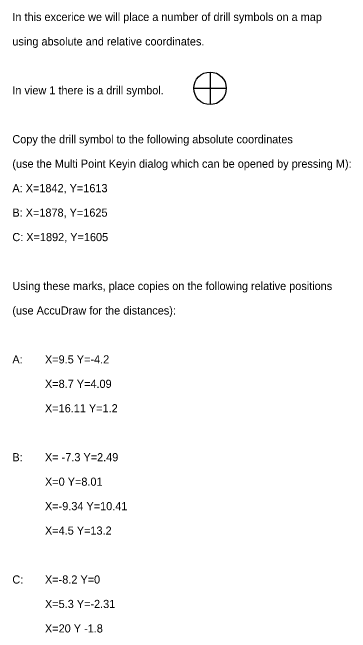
# Model space of a CAD drawing. Extents: x -2 to 1890, y 50 to 1639.
import ezdxf

# ---------------------------------------------------------------- set-up
doc = ezdxf.new("R2010")
doc.units = 0
doc.layers.add('Instruktioner', color=7, linetype='Continuous')

msp = doc.modelspace()

# ---------------------------------------------------------------- linework, layer by layer
at = {"layer": 'Instruktioner'}
for p, q in [((4.35, 66.804), (4.35, 65.804)), ((3.85, 66.304), (4.85, 66.304))]:
    msp.add_line(p, q, dxfattribs=at)
msp.add_circle((4.35, 66.304), 0.5, dxfattribs=at)

# ---------------------------------------------------------------- texts
for s, p in [('In this excerice we will place a number of drill symbols on a map', (-1.713, 68.368)), ('using absolute and relative coordinates.', (-1.713, 67.618)), ('In view 1 there is a drill symbol.', (-1.713, 66.118)), ('Copy the drill symbol to the following absolute coordinates', (-1.713, 64.618)), ('(use the Multi Point Keyin dialog which can be opened by pressing M):', (-1.713, 63.868)), ('A: X=1842, Y=1613 ', (-1.713, 63.118)), ('B: X=1878, Y=1625', (-1.713, 62.368)), ('C: X=1892, Y=1605', (-1.713, 61.618)), ('Using these marks, place copies on the following relative positions', (-1.713, 60.118)), ('(use AccuDraw for the distances):', (-1.713, 59.368)), ('A: ', (-1.713, 57.868)), ('X=9.5 Y=-4.2', (-0.713, 57.868)), ('X=8.7 Y=4.09', (-0.713, 57.118)), ('X=16.11 Y=1.2', (-0.713, 56.368)), ('B:', (-1.713, 54.868)), ('X= -7.3 Y=2.49', (-0.713, 54.868)), ('X=0 Y=8.01', (-0.713, 54.118)), ('X=-9.34 Y=10.41', (-0.713, 53.368)), ('X=4.5 Y=13.2 ', (-0.713, 52.618)), ('C:', (-1.713, 51.118)), ('X=-8.2 Y=0', (-0.713, 51.118)), ('X=5.3 Y=-2.31', (-0.713, 50.368)), ('X=20 Y -1.8', (-0.713, 49.618))]:
    msp.add_text(s, height=0.25, dxfattribs=at).set_placement(p)

doc.saveas('drawing.dxf')
